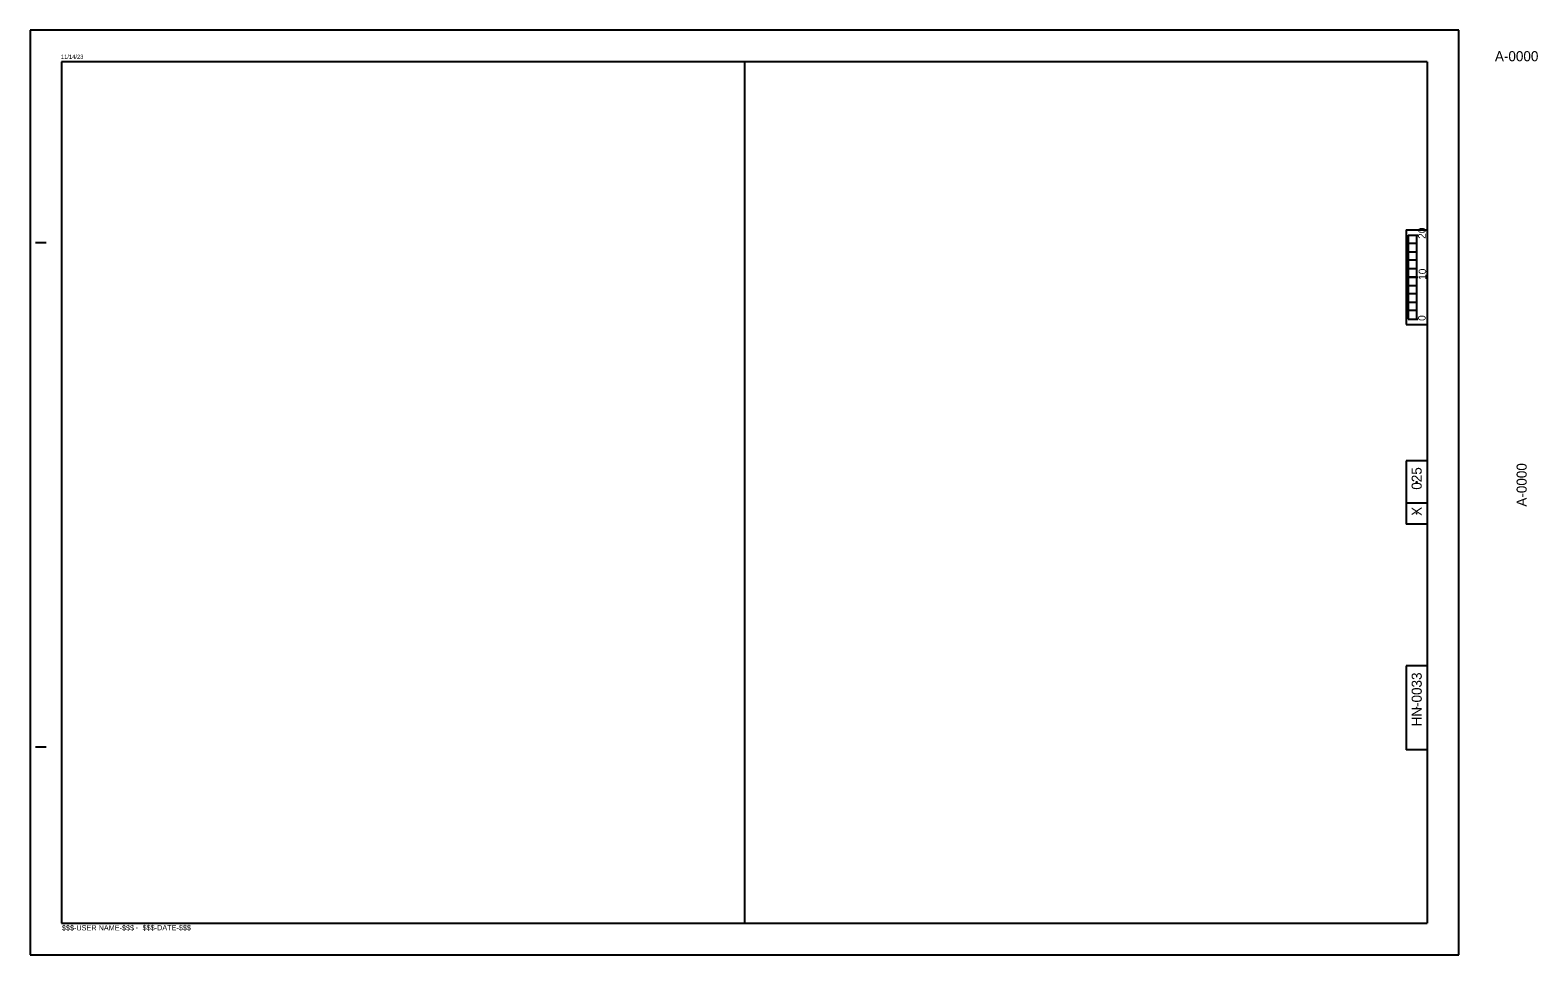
# Model space of a CAD drawing. Extents: x -2.69 to 2.99, y 0 to 1.83.
# Drawn here: x 0 to 2.99, y 0 to 1.833 of the extents above; entities that cross this region are included whole.
import ezdxf

# ---------------------------------------------------------------- set-up
doc = ezdxf.new("R2010")
doc.units = 0
for name, color, linetype in [('P_NCDOT_XS_Label_Finished_Grade', 7, 'Continuous'), ('P_NCDOT_XS_Leader_Line', 7, 'Continuous'), ('P_NCDOT_XS_Sheet_Grid_Border', 7, 'Continuous'), ('Sheet_Grid_Middle', 7, 'Continuous'), ('Sheet_Grid_Minor', 7, 'Continuous')]:
    doc.layers.add(name, color=color, linetype=linetype)

msp = doc.modelspace()

# ---------------------------------------------------------------- linework, layer by layer
at = {"layer": 'P_NCDOT_XS_Sheet_Grid_Border'}
for p, q in [((0.0625, 1.7708), (0.0625, 0.0625)), ((2.7708, 1.7708), (0.0625, 1.7708)), ((0.1027, 1.7844), (0.1027, 1.7844)), ((2.7708, 1.7708), (2.7708, 0.0625)), ((2.7292, 1.4375), (2.7292, 1.25)), ((2.7292, 1.4375), (2.7708, 1.4375)), ((0.0108, 1.4125), (0.0317, 1.4126)), ((2.7292, 1.25), (2.7708, 1.25)), ((2.7292, 0.9792), (2.7292, 0.8542)), ((2.7708, 0.9792), (2.7292, 0.9792)), ((2.7708, 0.8958), (2.7292, 0.8958)), ((2.7708, 0.8542), (2.7292, 0.8542)), ((2.7292, 0.5729), (2.7292, 0.4062)), ((2.7708, 0.5729), (2.7292, 0.5729)), ((0.0109, 0.4125), (0.0317, 0.4125)), ((2.7708, 0.4062), (2.7292, 0.4062)), ((0.0625, 0.0625), (2.7708, 0.0625))]:
    msp.add_line(p, q, dxfattribs=at)
at = {"layer": 'Sheet_Grid_Middle'}
for p, q in [((2.7332, 1.4272), (2.7521, 1.4272)), ((2.7332, 1.4272), (2.7332, 1.2605)), ((2.7416, 1.4272), (2.7503, 1.4272)), ((2.7499, 1.4272), (2.7499, 1.2605)), ((2.7332, 1.3438), (2.7521, 1.3438)), ((2.7332, 1.2605), (2.7521, 1.2605)), ((2.7416, 1.2605), (2.7503, 1.2605))]:
    msp.add_line(p, q, dxfattribs=at)
for points in [[(2.7332, 1.4272), (2.7499, 1.4272), (2.7499, 1.4105), (2.7332, 1.4105)], [(2.7332, 1.3938), (2.7499, 1.3938), (2.7499, 1.3772), (2.7332, 1.3772)], [(2.7332, 1.3605), (2.7499, 1.3605), (2.7499, 1.3438), (2.7332, 1.3438)], [(2.7332, 1.3272), (2.7499, 1.3272), (2.7499, 1.3105), (2.7332, 1.3105)], [(2.7332, 1.2938), (2.7499, 1.2938), (2.7499, 1.2772), (2.7332, 1.2772)]]:
    msp.add_lwpolyline(points, close=True, dxfattribs=at)
at = {"layer": 'Sheet_Grid_Minor'}
for p, q in [((2.8333, 1.8333), (0, 1.8333)), ((0, 1.8333), (0, 0)), ((2.8333, 0), (2.8333, 1.8333)), ((1.4167, 1.7708), (1.4166, 0.0625)), ((0, 0), (2.8333, 0))]:
    msp.add_line(p, q, dxfattribs=at)
for centre in [(2.7499, 1.3437), (2.7499, 0.9375), (2.7499, 0.875), (2.75, 0.4897)]:
    msp.add_circle(centre, 0.0001, dxfattribs=at)

# ---------------------------------------------------------------- texts
at = {"layer": 'P_NCDOT_XS_Label_Finished_Grade'}
msp.add_text('A-0000', height=0.02, dxfattribs=at).set_placement((2.9051, 1.7717))
for s, p in [('A-0000', (2.9681, 0.8886)), ('HN-0033', (2.76, 0.4528))]:
    msp.add_text(s, height=0.02, rotation=90, dxfattribs=at).set_placement(p)
at = {"layer": 'P_NCDOT_XS_Leader_Line'}
for s, p in [('025', (2.7599, 0.9222)), ('X', (2.7599, 0.8704))]:
    msp.add_text(s, height=0.02, rotation=90, dxfattribs=at).set_placement(p)
at = {"layer": 'P_NCDOT_XS_Sheet_Grid_Border'}
msp.add_text('11/14/23', height=0.00833, rotation=0, dxfattribs=at).set_placement((0.0609, 1.7764))
for s, height, p in [('$$$-DATE-$$$', 0.010417, (0.223, 0.0486)), ('$$$-USER NAME-$$$', 0.010417, (0.063, 0.0484)), ('-', 0.0104, (0.2093, 0.0494))]:
    msp.add_text(s, height=height, dxfattribs=at).set_placement(p)
at = {"layer": 'Sheet_Grid_Middle'}
for s, p in [('20', (2.7678, 1.4196)), ('10', (2.7688, 1.3382)), ('0', (2.7677, 1.2569))]:
    msp.add_text(s, height=0.015, rotation=90, dxfattribs=at).set_placement(p)

doc.saveas('drawing.dxf')
